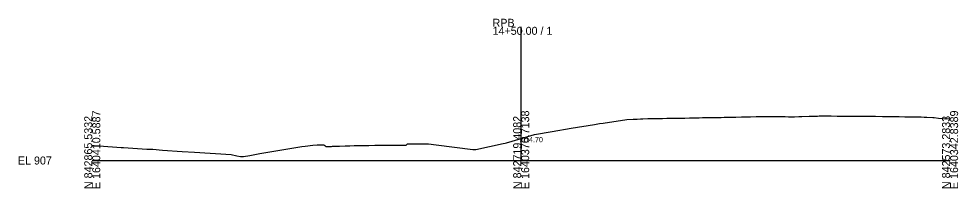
# Model space of a CAD drawing. Extents: x -26 to 1641030, y -10 to 842962.
# Drawn here: x -25.7 to 302.8, y 4490.3 to 4549.6 of the extents above; entities that cross this region are included whole.
import ezdxf

# ---------------------------------------------------------------- set-up
doc = ezdxf.new("R2010")
doc.units = 0
for name, color, linetype in [('Exist Cross Section Cell', 7, 'Continuous'), ('Exist XS Center Line Elevation Label', 7, 'Continuous'), ('Exist XS Ground Line', 7, 'Continuous')]:
    doc.layers.add(name, color=color, linetype=linetype)

msp = doc.modelspace()

# ---------------------------------------------------------------- linework, layer by layer
at = {"layer": 'Exist Cross Section Cell'}
for p, q in [((150, 4500), (150, 4546.76)), ((0, 4500), (150, 4500)), ((150, 4500), (300, 4500))]:
    msp.add_line(p, q, dxfattribs=at)
at = {"layer": 'Exist XS Ground Line'}
msp.add_lwpolyline([(0, 4505.29), (0.68, 4505.25), (2.46, 4505.14), (10.1, 4504.56), (10.95, 4504.5), (19.12, 4503.99), (21.22, 4503.92), (24.57, 4503.63), (31.48, 4503.17), (35.79, 4502.9), (48.6, 4502.05), (50.51, 4501.63), (51.83, 4501.38), (52.89, 4501.37), (55.07, 4501.8), (56.8, 4502.14), (58.58, 4502.41), (73.34, 4504.94), (74.45, 4505.07), (77.17, 4505.42), (78.71, 4505.45), (79.66, 4505.47), (80.98, 4505.49), (81.28, 4505.24), (81.67, 4504.92), (83.23, 4504.93), (83.66, 4504.94), (84.03, 4504.97), (85.63, 4505.02), (86.52, 4505.05), (88.44, 4505.11), (89.08, 4505.13), (90.13, 4505.16), (91.65, 4505.2), (93.47, 4505.22), (94.22, 4505.23), (94.98, 4505.25), (95.78, 4505.27), (96.78, 4505.28), (98.85, 4505.31), (99.35, 4505.32), (100.15, 4505.32), (101.92, 4505.34), (103.49, 4505.34), (104.48, 4505.34), (107.2, 4505.33), (107.83, 4505.34), (109.26, 4505.34), (109.8, 4505.34), (110.3, 4505.83), (115.03, 4505.83), (117.63, 4505.84), (120.22, 4505.52), (133.12, 4503.9), (133.69, 4503.9), (134.13, 4503.9), (143.68, 4505.94), (144.41, 4506.11), (144.85, 4506.21), (150, 4507.7), (154.67, 4509.04), (160.8, 4510.11), (167.46, 4511.29), (175.69, 4512.63), (177.44, 4512.89), (178.72, 4513.08), (186.98, 4514.34), (189.17, 4514.47), (190.52, 4514.5), (191.74, 4514.52), (192.6, 4514.55), (194.3, 4514.66), (195.75, 4514.69), (196.7, 4514.7), (197.03, 4514.72), (199.44, 4514.74), (200.94, 4514.78), (202, 4514.8), (203.71, 4514.81), (204.57, 4514.82), (205.1, 4514.83), (207.21, 4514.86), (208.84, 4514.9), (209.16, 4514.91), (209.7, 4514.92), (211.35, 4514.94), (212.27, 4514.96), (213.44, 4514.99), (214.83, 4515), (215.52, 4515), (217.6, 4515.03), (218.47, 4515.05), (219.97, 4515.08), (221.03, 4515.11), (222.53, 4515.15), (223.76, 4515.17), (225.1, 4515.2), (227.1, 4515.24), (227.66, 4515.26), (228.02, 4515.26), (229.54, 4515.29), (230.23, 4515.3), (232.19, 4515.35), (233.04, 4515.35), (234.11, 4515.34), (234.94, 4515.34), (235.36, 4515.34), (237.12, 4515.33), (237.93, 4515.33), (240.55, 4515.33), (242.31, 4515.34), (243.54, 4515.3), (244.99, 4515.27), (245.63, 4515.32), (247.14, 4515.36), (248.2, 4515.39), (250.76, 4515.46), (251.69, 4515.49), (253.66, 4515.55), (254.26, 4515.57), (255.89, 4515.59), (257.19, 4515.57), (258.46, 4515.57), (260.5, 4515.56), (261.03, 4515.56), (262.76, 4515.55), (263.59, 4515.55), (265.52, 4515.54), (266.12, 4515.54), (266.79, 4515.53), (267.63, 4515.52), (268.73, 4515.51), (269.69, 4515.5), (271.29, 4515.49), (271.77, 4515.49), (273.87, 4515.46), (276.42, 4515.43), (277.02, 4515.43), (278.64, 4515.42), (279.09, 4515.41), (280.7, 4515.37), (281.56, 4515.35), (282.19, 4515.34), (284.12, 4515.32), (284.9, 4515.31), (286.69, 4515.28), (288.44, 4515.25), (289.26, 4515.24), (289.87, 4515.22), (290.92, 4515.19), (291.82, 4515.17), (293.91, 4515.04), (294.39, 4515.01), (295.97, 4514.85), (297.25, 4514.73), (299.52, 4514.59), (300, 4514.56)], dxfattribs=at)

# ---------------------------------------------------------------- texts
at = {"layer": 'Exist Cross Section Cell'}
for s, p in [('14+50.00 / 1', (140, 4543.96)), ('RPB', (140, 4546.76)), ('EL 907', (-26, 4498.6))]:
    msp.add_text(s, height=2.8, dxfattribs=at).set_placement(p)
for s, p in [('N 842865.5332', (0, 4490)), ('E 1640410.5887', (2.8, 4490)), ('N 842719.4082', (150, 4490)), ('E 1640376.7138', (152.8, 4490)), ('N 842573.2833', (300, 4490)), ('E 1640342.8389', (302.8, 4490))]:
    msp.add_text(s, height=2.8, rotation=90, dxfattribs=at).set_placement(p)
at = {"layer": 'Exist XS Center Line Elevation Label'}
msp.add_text('914.70', height=1.8, dxfattribs=at).set_placement((150, 4506.4))

doc.saveas('drawing.dxf')
